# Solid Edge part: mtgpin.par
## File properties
Title: Mounting Pin
Subject: Carrier Assembly
Author: edge
Keywords: Mounting Pin
Comments: Mounting Pin
Template: metric.par
Last saved by: edge
Revision: 32
Application: Solid Edge
File Size: 0
Number of Sheets: 0
Number of Objects: 0
Username: edge
文書内容のタイプ: 0
Material: Copper
Face Style: Copper
Fill Style: ANSI33(Brass)
Virtual Style: Copper
Coef. of Thermal Exp: 1.8e-05
Thermal Conductivity: 391.0
Specific Heat: 385.0
Modulus of Elasticity: 117210869000.0
Poisson's Ratio: 0.31
Yield Stress: 275790280.0
Ultimate Stress: 310264065.0
Elongation: 0.0
Category: Macined Cylindrical
Manager: Brian Little
Company: Wheels R Us
Density: 8906
Accuracy: 0.99
Document Number: MP-101
Revision: 1
Project Name: Trolley Wheel Assembly
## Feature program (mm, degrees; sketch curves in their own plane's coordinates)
sketch for "unnamed RevolvedProtrusion 1" plane through (0, 0, 0) normal (0, -1, 0) x-axis (1, 0, 0)
  line (-56.4485, 0) -> (-56.4485, 10.25)
  line (-56.4485, 10.25) -> (-6.4485, 10.25)
  line (-6.4485, 10.25) -> (-6.4485, 18)
  line (-6.4485, 18) -> (5.5515, 18)
  line (5.5515, 18) -> (5.5515, 0)
  line (5.5515, 0) -> (-56.4485, 0)
revolve "unnamed RevolvedProtrusion 1" add finite 360 deg about sketch line (21.325, 0) -> (44.5316, 0)
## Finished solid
Body 1: solid body, 5 faces, 4 edges, 0 vertices.
  Faces by surface: plane 3, cylinder 2
  Edges by curve: circle 4
Bounding box of the edges (mm): 62.000 x 36.000 x 36.000, from (-56.4485, -18, -18) to (5.5515, 18, 18).
Cylindrical faces by radius (mm): R10.25 x1, R18 x1
Planar faces by outward normal: +x 1, -x 2
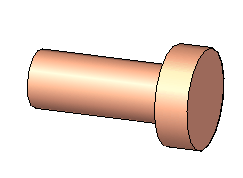
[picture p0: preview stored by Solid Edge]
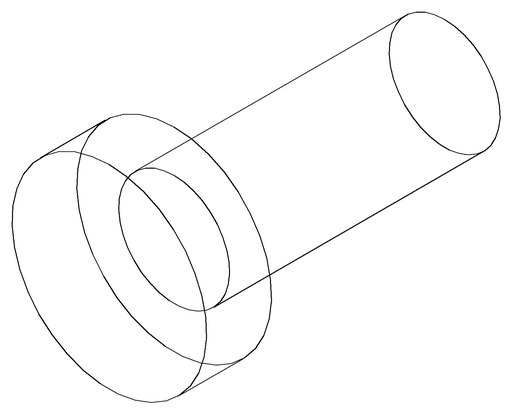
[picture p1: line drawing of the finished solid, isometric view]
